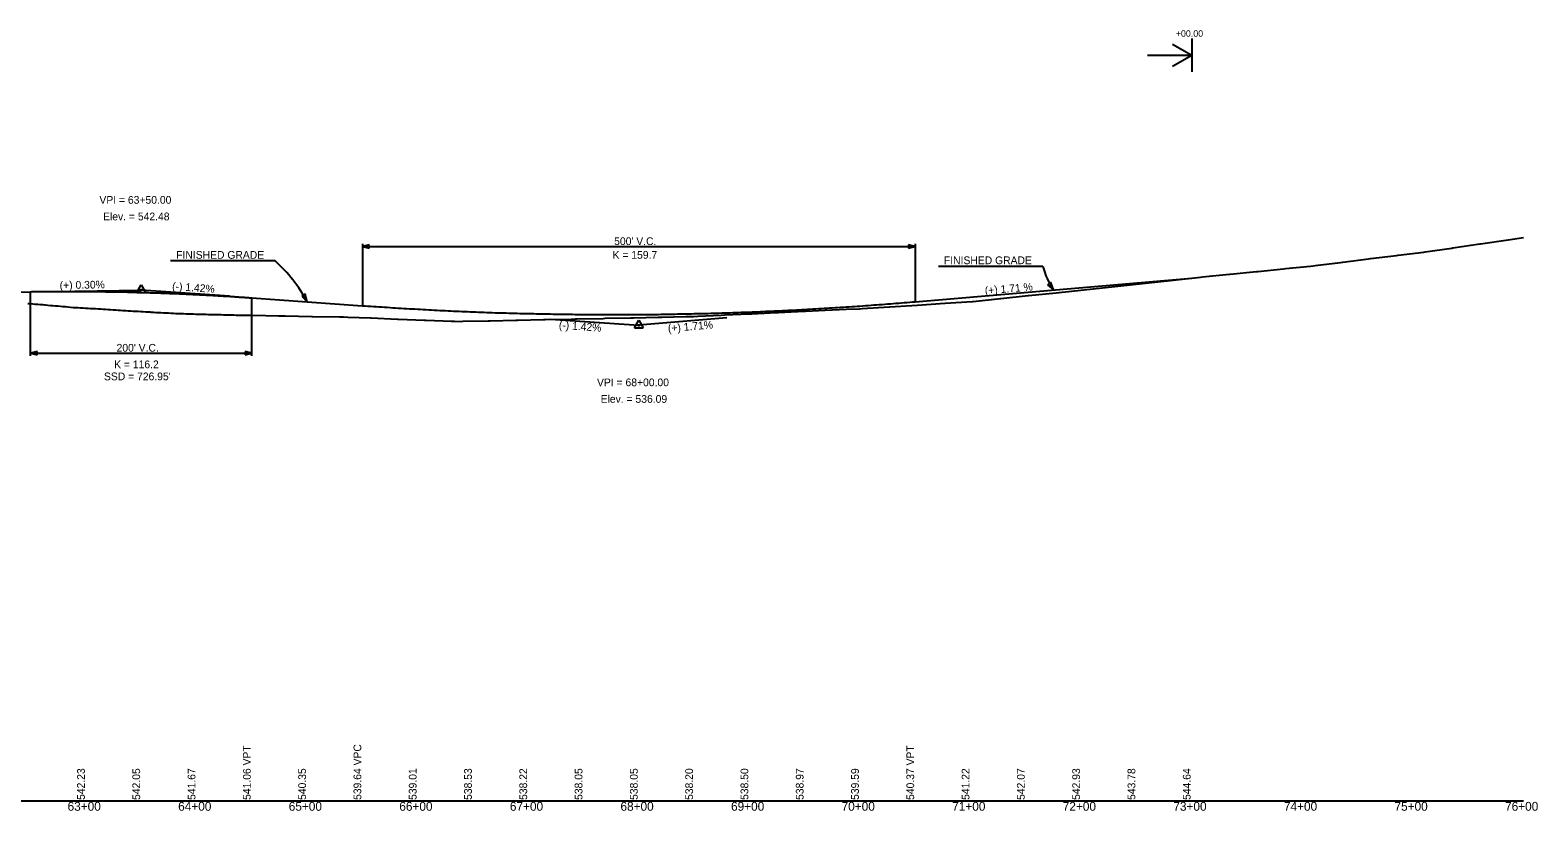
# Model space of a CAD drawing. Extents: x 49922 to 52613, y 49991 to 60509.
# Drawn here: x 51250 to 52613, y 49991 to 50698 of the extents above; entities that cross this region are included whole.
import ezdxf

# ---------------------------------------------------------------- set-up
doc = ezdxf.new("R2010")
doc.units = 0
for name, color, linetype in [('RD_DDB_GradeTX', 7, 'Continuous'), ('RD_DDB_Profile_EX', 7, 'Continuous'), ('RD_DDB_Profile_Lbl', 7, 'Continuous'), ('RD_DDB_Profile_PR', 7, 'Continuous'), ('RD_DDB_StaTX', 7, 'Continuous'), ('RD_DDB_StripGrade', 7, 'Continuous'), ('RD_DDB_VCLbl', 7, 'Continuous'), ('RD_GPK_Profile_Cell', 7, 'Continuous'), ('RD_TX_Profile', 7, 'Continuous')]:
    doc.layers.add(name, color=color, linetype=linetype)

msp = doc.modelspace()

# ---------------------------------------------------------------- linework, layer by layer
at = {"layer": 'RD_DDB_GradeTX'}
for p, q in [((51556, 50503.3), (51550, 50501.8)), ((51550, 50501.8), (51556, 50500.3)), ((51556, 50500.3), (51556, 50503.3)), ((52050, 50501.8), (52044, 50503.3)), ((52044, 50503.3), (52044, 50500.3)), ((52044, 50500.3), (52050, 50501.8)), ((51346, 50460.1), (51350, 50467)), ((51350, 50467), (51354, 50460.1)), ((51270, 50461.2), (51350, 50462.4)), ((51346, 50460.1), (51354, 50460.1)), ((51429.8, 50456.8), (51350, 50462.4)), ((51720.2, 50436.1), (51800, 50430.5)), ((51879.7, 50437.3), (51800, 50430.5)), ((51796, 50428.2), (51800, 50435)), ((51796, 50428.2), (51804, 50428.2)), ((51800, 50435), (51804, 50428.2)), ((51256, 50406.8), (51250, 50405.3)), ((51250, 50405.3), (51256, 50403.8)), ((51256, 50403.8), (51256, 50406.8)), ((51450, 50405.3), (51444, 50406.8)), ((51444, 50406.8), (51444, 50403.8)), ((51444, 50403.8), (51450, 50405.3))]:
    msp.add_line(p, q, dxfattribs=at)
for centre in [(51350, 50462.4), (51800, 50430.5)]:
    msp.add_circle(centre, 0.529, dxfattribs=at)
at = {"layer": 'RD_DDB_Profile_EX'}
for points in [[(51877.8, 50439.8), (51899.6, 50440.8), (51902.1, 50440.9), (51924.6, 50442), (51926.4, 50442.1), (51949.6, 50443.2), (51950.7, 50443.2), (51974.7, 50444.4), (51975, 50444.4), (51987.6, 50445), (51999.4, 50445.5), (51999.7, 50445.5), (52002, 50445.6), (52026.6, 50447.2), (52027, 50447.2), (52051.6, 50448.8), (52052, 50448.8), (52076.6, 50450.4), (52077, 50450.5), (52101.6, 50452), (52102, 50452.1), (52102.5, 50452.1), (52127.1, 50454.7), (52127.5, 50454.7), (52152.2, 50457.3), (52152.5, 50457.3), (52177.5, 50459.9), (52202.5, 50462.5), (52208.2, 50463.1), (52233.2, 50465.9), (52258.2, 50468.6), (52283.2, 50471.4), (52308.1, 50474.1), (52309.8, 50474.3), (52334.1, 50476.7), (52334.9, 50476.8), (52358.6, 50479.2), (52359.9, 50479.3), (52383, 50481.7), (52384.9, 50481.9), (52407.5, 50484.1), (52410, 50484.4), (52411.8, 50484.6), (52434.6, 50487.4), (52436.8, 50487.7), (52459.9, 50490.5), (52461.8, 50490.8), (52485.2, 50493.7), (52486.8, 50493.9), (52510, 50496.7), (52511.2, 50496.9), (52535.3, 50500.4), (52536.2, 50500.5), (52560.6, 50504.1), (52561.2, 50504.2), (52586.3, 50507.8), (52600, 50509.9)], [(51247.4, 50450.2), (51249.7, 50450.1), (51252, 50449.9), (51254.2, 50449.7), (51256.5, 50449.5), (51258.8, 50449.4), (51261, 50449.2), (51262.8, 50449), (51263.3, 50449), (51265.6, 50448.8), (51267.9, 50448.5), (51270.1, 50448.4), (51272.4, 50448.2), (51274.7, 50448), (51276.9, 50447.8), (51279.2, 50447.6), (51281.5, 50447.4), (51283.7, 50447.2), (51286, 50447), (51288.5, 50446.7), (51290.6, 50446.6), (51292.8, 50446.5), (51295.1, 50446.4), (51297.4, 50446.3), (51299.6, 50446.1), (51301.9, 50446), (51304.2, 50445.8), (51306.4, 50445.7), (51308.7, 50445.6), (51311, 50445.4), (51312.1, 50445.4), (51313.5, 50445.3), (51315.5, 50445.1), (51317.8, 50445), (51320.1, 50444.8)], [(51320.1, 50444.8), (51322.3, 50444.7), (51324.6, 50444.5), (51326.9, 50444.4), (51329.2, 50444.2), (51331.4, 50444.1), (51333.4, 50443.9), (51333.7, 50443.9), (51336, 50443.8), (51338.2, 50443.7), (51340.5, 50443.6), (51342.8, 50443.4), (51345, 50443.3), (51347.3, 50443.2), (51349.6, 50443.1), (51351.9, 50442.9), (51354.1, 50442.8), (51356.4, 50442.7), (51358.3, 50442.6), (51358.7, 50442.5), (51360.9, 50442.4), (51361.3, 50442.3), (51363.2, 50442.2), (51365.5, 50442.1), (51367.7, 50442), (51370, 50441.8), (51372.3, 50441.7), (51374.6, 50441.6), (51376.8, 50441.5), (51379.3, 50441.3), (51381.4, 50441.2), (51383.6, 50441.1), (51385.9, 50441), (51388.2, 50441), (51390.5, 50440.9), (51392.7, 50440.8), (51395, 50440.8), (51397.3, 50440.7), (51399.5, 50440.6), (51401.8, 50440.6), (51404.3, 50440.5), (51406.3, 50440.5), (51408.6, 50440.4), (51410.9, 50440.3), (51413.2, 50440.3), (51415.4, 50440.2), (51417.7, 50440.2), (51420, 50440.1), (51422.2, 50440.1), (51424.5, 50440), (51425.8, 50439.9), (51426.8, 50439.9), (51429.1, 50439.8), (51431.3, 50439.8), (51433.6, 50439.8), (51435.9, 50439.7), (51438.1, 50439.7), (51440.4, 50439.7), (51447.7, 50439.5), (51450.7, 50439.5), (51474.3, 50439.1), (51475.9, 50439.1), (51479.2, 50439), (51480.3, 50439), (51504.2, 50438.5), (51504.8, 50438.5), (51529.3, 50438.1), (51532.9, 50438), (51536.7, 50437.9), (51557.3, 50437.1), (51557.8, 50437.1), (51581.8, 50436.1), (51582.8, 50436.1), (51606.2, 50435.2), (51607.8, 50435.2), (51630.7, 50434.3), (51632.8, 50434.2), (51633.2, 50434.2), (51638.6, 50434), (51640.9, 50434.1), (51663.7, 50434.5), (51665.7, 50434.6), (51688.7, 50435.1), (51690.5, 50435.1), (51713.7, 50435.6), (51715.3, 50435.6), (51738.9, 50436.1), (51742.7, 50436.2), (51744, 50436.2), (51767.7, 50436.7), (51769.6, 50436.8), (51792.7, 50437.2), (51795.3, 50437.3), (51817.6, 50437.8), (51820.9, 50437.8), (51842.6, 50438.3), (51843.6, 50438.3), (51849.5, 50438.4), (51853.4, 50438.6), (51874.5, 50439.6), (51877.8, 50439.8)]]:
    msp.add_lwpolyline(points, dxfattribs=at)
at = {"layer": 'RD_DDB_Profile_PR'}
for p, q in [((52050, 50451.8), (52300, 50473.2)), ((50875, 50455.3), (51250, 50460.9)), ((51450, 50455.3), (51550, 50448.2))]:
    msp.add_line(p, q, dxfattribs=at)
for points in [[(51250, 50460.9), (51254, 50461), (51258, 50461), (51262, 50461.1), (51266, 50461.1), (51270, 50461.1), (51274, 50461.2), (51278, 50461.2), (51282, 50461.2), (51286, 50461.2), (51290, 50461.2), (51294, 50461.2), (51298, 50461.1), (51302, 50461.1), (51306, 50461.1), (51310, 50461), (51314, 50461), (51318, 50460.9), (51322, 50460.9), (51326, 50460.8), (51330, 50460.7), (51334, 50460.7), (51338, 50460.6), (51342, 50460.5), (51346, 50460.4), (51350, 50460.3), (51354, 50460.2), (51358, 50460), (51362, 50459.9), (51366, 50459.8), (51370, 50459.6), (51374, 50459.5), (51378, 50459.3), (51382, 50459.2), (51386, 50459), (51390, 50458.8), (51394, 50458.6), (51398, 50458.4), (51402, 50458.2), (51406, 50458), (51410, 50457.8), (51414, 50457.6), (51418, 50457.4), (51422, 50457.1), (51426, 50456.9), (51430, 50456.7), (51434, 50456.4), (51438, 50456.1), (51442, 50455.9), (51446, 50455.6), (51450, 50455.3)], [(51550, 50448.2), (51560, 50447.5), (51570, 50446.9), (51580, 50446.2), (51590, 50445.6), (51600, 50445.1), (51610, 50444.5), (51620, 50444), (51630, 50443.5), (51640, 50443.1), (51650, 50442.7), (51660, 50442.3), (51670, 50441.9), (51680, 50441.6), (51690, 50441.3), (51700, 50441.1), (51710, 50440.9), (51720, 50440.7), (51730, 50440.5), (51740, 50440.4), (51750, 50440.3), (51760, 50440.2), (51770, 50440.2), (51780, 50440.2), (51790, 50440.2), (51800, 50440.2), (51810, 50440.3), (51820, 50440.4), (51830, 50440.6), (51840, 50440.8), (51850, 50441), (51860, 50441.2), (51870, 50441.5), (51880, 50441.8), (51890, 50442.2), (51900, 50442.5), (51910, 50442.9), (51920, 50443.4), (51930, 50443.8), (51940, 50444.3), (51950, 50444.8), (51960, 50445.4), (51970, 50446), (51980, 50446.6), (51990, 50447.3), (52000, 50447.9), (52010, 50448.7), (52020, 50449.4), (52030, 50450.2), (52040, 50451), (52050, 50451.8)]]:
    msp.add_spline(points, degree=3, dxfattribs=at)
at = {"layer": 'RD_DDB_VCLbl'}
for p, q in [((51550, 50504.3), (51550, 50448.2)), ((52050, 50504.3), (52050, 50451.8)), ((51550, 50501.8), (52050, 50501.8)), ((51250, 50402.8), (51250, 50460.9)), ((51450, 50402.8), (51450, 50455.3)), ((51250, 50405.3), (51450, 50405.3))]:
    msp.add_line(p, q, dxfattribs=at)
at = {"layer": 'RD_GPK_Profile_Cell'}
msp.add_line((50000, 50000), (52600, 50000), dxfattribs=at)
at = {"layer": 'RD_TX_Profile'}
for p, q in [((52282.7, 50685), (52300, 50675)), ((52300, 50690), (52300, 50660)), ((52260, 50675), (52300, 50675)), ((52282.7, 50665), (52300, 50675)), ((51471.1, 50488.7), (51376.6, 50488.7)), ((52165.4, 50483.8), (52070.9, 50483.8))]:
    msp.add_line(p, q, dxfattribs=at)
for points in [[(52169.7, 50467.1), (52175, 50462.5), (52172.7, 50469.1)], [(51495.2, 50456.9), (51500, 50451.8), (51498.4, 50458.6)]]:
    msp.add_lwpolyline(points, close=True, dxfattribs=at)
for centre, radius, start, end in [((51380.3, 50387.9), 135.7, 28.0786, 47.972), ((52229.3, 50499.7), 65.8, 194.0218, 214.4266)]:
    msp.add_arc(centre, radius, start, end, dxfattribs=at)

# ---------------------------------------------------------------- texts
at = {"layer": 'RD_DDB_GradeTX'}
for s, rotation, p in [('(+) 0.30%', 0.8594, (51276.3, 50463.3)), ('(-) 1.42%', 355.9359, (51377.8, 50462.5)), ('(+) 1.71 %', 4.8869, (52113.2, 50458.4)), ('(-) 1.42%', 355.9359, (51727.5, 50427.4)), ('(+) 1.71%', 4.8869, (51826.6, 50424.2))]:
    msp.add_text(s, height=7, rotation=rotation, dxfattribs=at).set_placement(p)
at = {"layer": 'RD_DDB_Profile_Lbl'}
for s, p in [('VPI = 63+50.00', (51312.2, 50540.5)), ('Elev. = 542.48', (51315.5, 50525.5)), ('VPI = 68+00.00', (51762.2, 50375.3)), ('Elev. = 536.09', (51765.5, 50360.3))]:
    msp.add_text(s, height=7, dxfattribs=at).set_placement(p)
at = {"layer": 'RD_DDB_StaTX'}
for s, p in [('63+00', (51283.4, 49991)), ('64+00', (51383.4, 49991)), ('65+00', (51483.4, 49991)), ('66+00', (51583.4, 49991)), ('67+00', (51683.4, 49991)), ('68+00', (51783.4, 49991)), ('69+00', (51883.4, 49991)), ('70+00', (51983.4, 49991)), ('71+00', (52083.4, 49991)), ('72+00', (52183.4, 49991)), ('73+00', (52283.4, 49991)), ('74+00', (52383.4, 49991)), ('75+00', (52483.4, 49991)), ('76+00', (52583.4, 49991))]:
    msp.add_text(s, height=8, dxfattribs=at).set_placement(p)
at = {"layer": 'RD_DDB_StripGrade'}
for s, p in [('541.06 VPT', (51449, 50000.8)), ('539.64 VPC', (51549, 50000.8)), ('540.37 VPT', (52049, 50000.8)), ('542.23', (51299, 50000.8)), ('542.05', (51349, 50000.8)), ('541.67', (51399, 50000.8)), ('541.06', (51449, 50000.8)), ('540.35', (51499, 50000.8)), ('539.64', (51549, 50000.8)), ('539.01', (51599, 50000.8)), ('538.53', (51649, 50000.8)), ('538.22', (51699, 50000.8)), ('538.05', (51749, 50000.8)), ('538.05', (51799, 50000.8)), ('538.20', (51849, 50000.8)), ('538.50', (51899, 50000.8)), ('538.97', (51949, 50000.8)), ('539.59', (51999, 50000.8)), ('540.37', (52049, 50000.8)), ('541.22', (52099, 50000.8)), ('542.07', (52149, 50000.8)), ('542.93', (52199, 50000.8)), ('543.78', (52249, 50000.8)), ('544.64', (52299, 50000.8))]:
    msp.add_text(s, height=7, rotation=90, dxfattribs=at).set_placement(p)
at = {"layer": 'RD_DDB_VCLbl'}
for s, p in [("500' V.C.", (51777.7, 50503.1)), ('K = 159.7', (51776.3, 50490.7)), ("200' V.C.", (51327.7, 50406.6)), ('K = 116.2', (51325.5, 50391.6)), ("SSD = 726.95'", (51316.3, 50380.7))]:
    msp.add_text(s, height=7, dxfattribs=at).set_placement(p)
at = {"layer": 'RD_TX_Profile'}
for s, height, p in [('+00.00', 6, (52285.6, 50691.6)), ('FINISHED GRADE', 7, (51381.6, 50490.7)), ('FINISHED GRADE', 7, (52075.9, 50485.8))]:
    msp.add_text(s, height=height, dxfattribs=at).set_placement(p)

doc.saveas('drawing.dxf')
